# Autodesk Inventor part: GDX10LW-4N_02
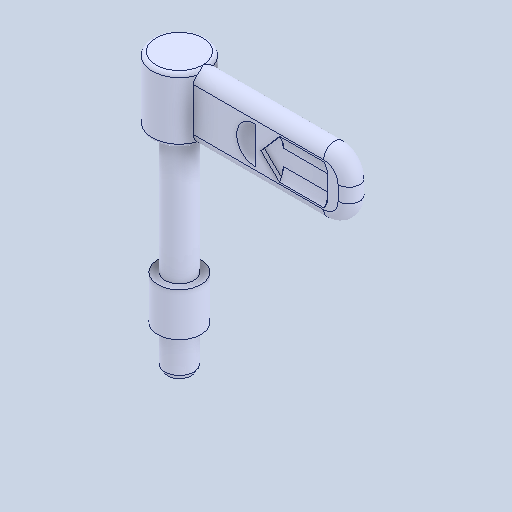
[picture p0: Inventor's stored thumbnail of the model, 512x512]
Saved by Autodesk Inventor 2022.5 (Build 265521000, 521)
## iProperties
Created: 2024-06
Part Number: GDX10LW-4N_02
Material: 一般
Document SubType Name: Modeling
Designer: ImaoCorp
Density: 1 g/cm^3
Appearance: 既定
Author: ImaoCorp
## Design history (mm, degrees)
feature "GDX10LW-4N_02"
node "ソリッド1"
